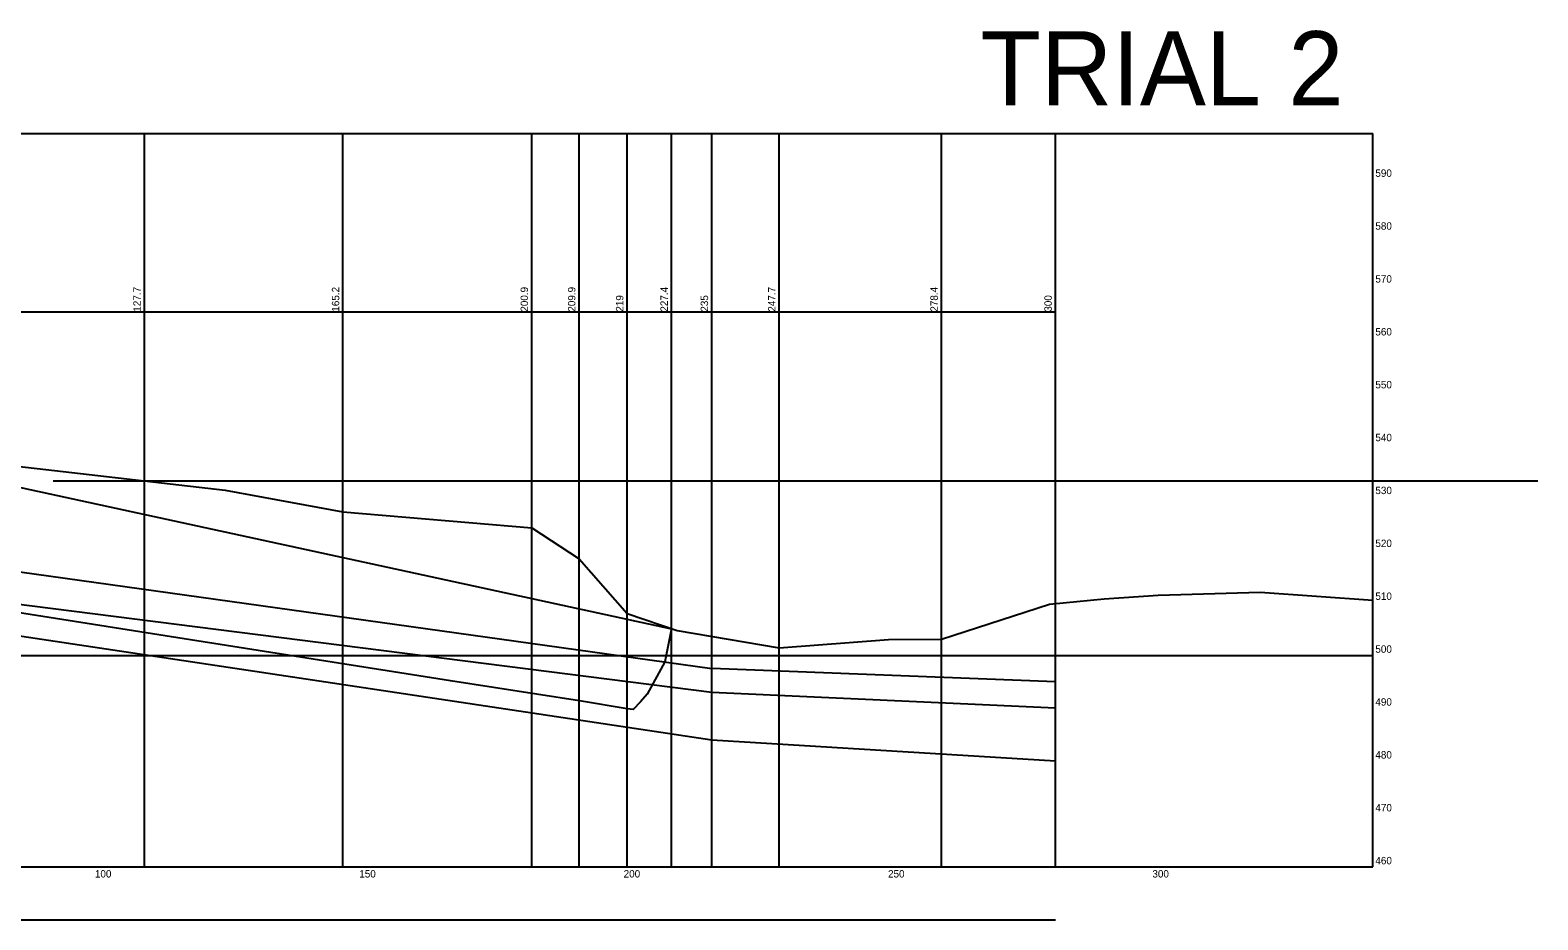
# Model space of a CAD drawing. Extents: x -64 to 1064, y -32 to 640.
# Drawn here: x 86.1 to 371.2, y 225.9 to 394.1 of the extents above; entities that cross this region are included whole.
import ezdxf

# ---------------------------------------------------------------- set-up
doc = ezdxf.new("R2010")
doc.units = 0
for name, color, linetype in [('DR_X_Headwall', 7, 'Continuous'), ('GT_Project_Soil_Layers', 7, 'Continuous'), ('GT_X_Shear_Surface', 7, 'Continuous'), ('SC_Scratch1', 7, 'Continuous'), ('SH_Major_Grid_Line', 7, 'Continuous'), ('SH_Text', 7, 'Continuous')]:
    doc.layers.add(name, color=color, linetype=linetype)

msp = doc.modelspace()

# ---------------------------------------------------------------- linework, layer by layer
at = {"layer": 'DR_X_Headwall'}
msp.add_lwpolyline([(25, 331.46), (25, 320.51), (207.39, 280.92)], dxfattribs=at)
at = {"layer": 'GT_Project_Soil_Layers'}
for p, q in [((280, 270.88), (215, 273.38)), ((280, 265.88), (215, 268.88)), ((280, 255.88), (215, 259.88))]:
    msp.add_line(p, q, dxfattribs=at)
for points in [[(-60, 322.49), (8.4, 304.98), (35.75, 298.45), (215, 273.38)], [(215, 268.88), (35.75, 291.63), (8.4, 298.48), (-59.7, 314.56)], [(215, 259.88), (35.75, 286.78), (8.4, 293.48), (-59.7, 310.12)]]:
    msp.add_lwpolyline(points, dxfattribs=at)
at = {"layer": 'GT_X_Shear_Surface'}
msp.add_lwpolyline([(207.4, 280.98), (206.1, 274.68), (202.8, 268.58), (201.5, 267.08), (200.1, 265.68), (199, 265.78), (190, 267.28), (165.6, 271.08), (139.6, 275.18), (112.8, 279.38), (66.5, 286.68), (20.9, 293.78), (8.4, 295.78), (-4.3, 297.78), (-8.7, 298.48), (-9.6, 300.28), (-10.3, 302.08), (-10.6, 302.98), (-10.9, 303.98), (-11.3, 305.98), (-11.6, 307.98), (-11.7, 309.98), (-12.51, 332.34)], dxfattribs=at)
at = {"layer": 'SC_Scratch1'}
msp.add_line((90.43, 308.88), (371.23, 308.88), dxfattribs=at)
msp.add_lwpolyline([(66.55, 313.64), (122.96, 307.11), (145.24, 303), (180.94, 299.98), (189.9, 294.16), (198.97, 283.83), (208.46, 280.56), (227.74, 277.32), (248.39, 278.88), (258.45, 278.95), (278.85, 285.54), (289.2, 286.6), (299.44, 287.28), (318.74, 287.87), (340, 286.32)], dxfattribs=at)
at = {"layer": 'SH_Major_Grid_Line'}
for p, q in [((-60, 374.58), (340, 374.58)), ((107.7, 235.88), (107.7, 374.58)), ((145.24, 235.88), (145.24, 374.58)), ((180.94, 235.88), (180.94, 374.58)), ((189.9, 235.88), (189.9, 374.58)), ((198.97, 235.88), (198.97, 374.58)), ((207.39, 235.88), (207.39, 374.58)), ((215, 235.88), (215, 374.58)), ((227.74, 235.88), (227.74, 374.58)), ((258.45, 235.88), (258.45, 374.58)), ((280, 235.88), (280, 374.58)), ((340, 235.88), (340, 374.58)), ((-60, 340.88), (280, 340.88)), ((-60, 275.88), (340, 275.88)), ((-60, 235.88), (340, 235.88)), ((-60, 225.88), (280, 225.88))]:
    msp.add_line(p, q, dxfattribs=at)

# ---------------------------------------------------------------- texts
at = {"layer": 'GT_Project_Soil_Layers'}
msp.add_text('TRIAL 2', height=14, dxfattribs=at).set_placement((265.8, 379.91))
for s, p in [('127.7', (107, 340.88)), ('165.2', (144.54, 340.88)), ('200.9', (180.24, 340.88)), ('209.9', (189.2, 340.88)), ('227.4', (206.69, 340.88)), ('247.7', (227.04, 340.88)), ('278.4', (257.75, 340.88)), ('219', (198.27, 340.88)), ('235', (214.3, 340.88)), ('300', (279.3, 340.88))]:
    msp.add_text(s, height=1.4, rotation=90, dxfattribs=at).set_placement(p)
at = {"layer": 'SH_Text'}
for s, p in [('590', (340.5, 366.38)), ('580', (340.5, 356.38)), ('570', (340.5, 346.38)), ('560', (340.5, 336.38)), ('550', (340.5, 326.38)), ('540', (340.5, 316.38)), ('530', (340.5, 306.38)), ('520', (340.5, 296.38)), ('510', (340.5, 286.38)), ('500', (340.5, 276.38)), ('490', (340.5, 266.38)), ('480', (340.5, 256.38)), ('470', (340.5, 246.38)), ('460', (340.5, 236.38)), ('100', (98.33, 233.88)), ('150', (148.33, 233.88)), ('200', (198.33, 233.88)), ('250', (248.33, 233.88)), ('300', (298.33, 233.88))]:
    msp.add_text(s, height=1.4, dxfattribs=at).set_placement(p)

doc.saveas('drawing.dxf')
